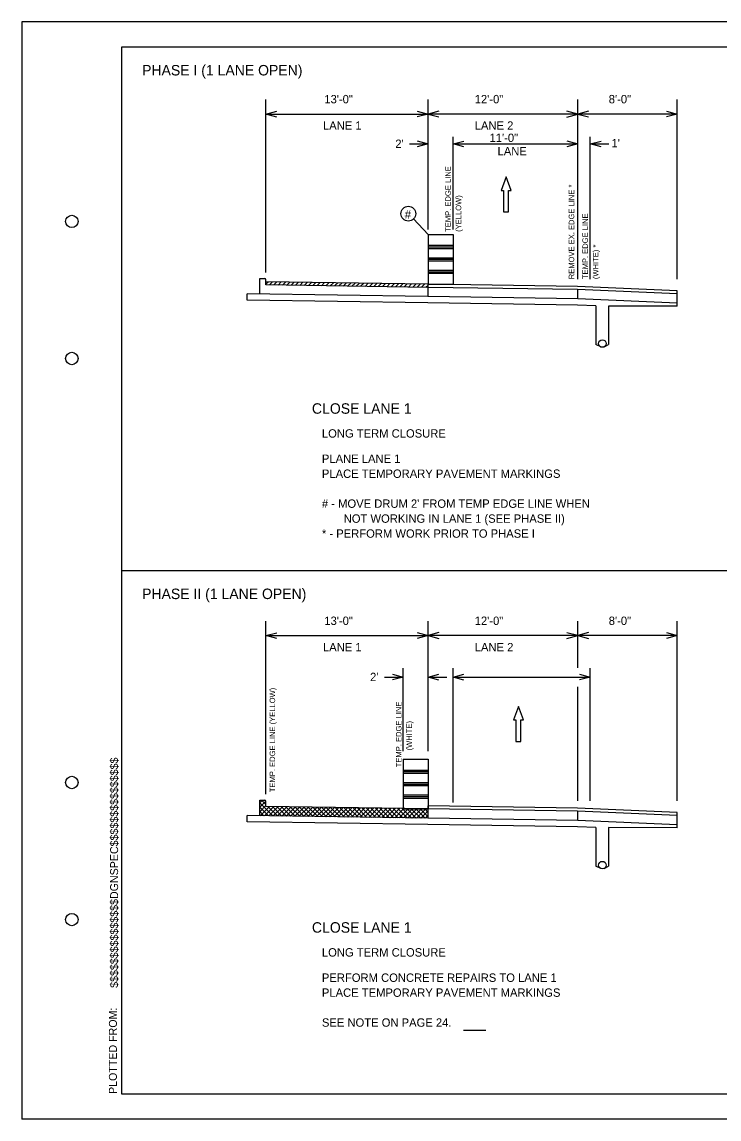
# Model space of a CAD drawing. Extents: x -161 to 291, y -369 to 173.
# Drawn here: x -160.7 to -104.8, y -273.4 to -185.4 of the extents above; entities that cross this region are included whole.
import ezdxf

# ---------------------------------------------------------------- set-up
doc = ezdxf.new("R2010")
doc.units = 0
for name, color, linetype in [('Level 1', 7, 'Continuous'), ('Level 11', 7, 'Continuous'), ('Level 21', 7, 'Continuous'), ('Level 25', 7, 'Continuous'), ('Level 26', 7, 'Continuous'), ('Level 6', 7, 'Continuous'), ('Level 7', 7, 'Continuous')]:
    doc.layers.add(name, color=color, linetype=linetype)

msp = doc.modelspace()

# ---------------------------------------------------------------- linework, layer by layer
at = {"layer": 'Level 1'}
for p, q in [((-160.725, -185.431), (-160.725, -273.422)), ((-24.739, -185.431), (-160.725, -185.431)), ((-152.726, -271.422), (-152.726, -187.43)), ((-152.726, -187.43), (-26.739, -187.43)), ((-152.726, -229.426), (-30.738, -229.426)), ((-26.739, -271.422), (-152.726, -271.422)), ((-24.739, -273.422), (-160.725, -273.422))]:
    msp.add_line(p, q, dxfattribs=at)
for centre in [(-156.725, -201.429), (-156.725, -212.428), (-156.725, -246.424), (-156.725, -257.423)]:
    msp.add_circle(centre, 0.5, dxfattribs=at)
at = {"layer": 'Level 11'}
for p, q in [((-141.66, -207.256), (-141.66, -206.015)), ((-141.66, -206.015), (-141.243, -206.015)), ((-141.16, -206.515), (-141.16, -206.098)), ((-128.16, -206.466), (-141.16, -206.265)), ((-141.16, -206.448), (-140.981, -206.268)), ((-128.16, -206.716), (-141.16, -206.515)), ((-140.879, -206.52), (-140.633, -206.274)), ((-140.531, -206.525), (-140.284, -206.279)), ((-140.182, -206.531), (-139.936, -206.284)), ((-139.834, -206.536), (-139.588, -206.29)), ((-139.486, -206.541), (-139.24, -206.295)), ((-139.138, -206.547), (-138.892, -206.301)), ((-138.79, -206.552), (-138.543, -206.306)), ((-138.442, -206.557), (-138.195, -206.311)), ((-138.093, -206.563), (-137.847, -206.317)), ((-137.745, -206.568), (-137.499, -206.322)), ((-137.397, -206.574), (-137.151, -206.327)), ((-137.049, -206.579), (-136.803, -206.333)), ((-136.701, -206.584), (-136.454, -206.338)), ((-136.352, -206.59), (-136.106, -206.344)), ((-136.004, -206.595), (-135.758, -206.349)), ((-135.656, -206.6), (-135.41, -206.354)), ((-135.308, -206.606), (-135.062, -206.36)), ((-134.96, -206.611), (-134.714, -206.365)), ((-134.612, -206.617), (-134.365, -206.37)), ((-134.263, -206.622), (-134.017, -206.376)), ((-133.915, -206.627), (-133.669, -206.381)), ((-133.567, -206.633), (-133.321, -206.387)), ((-133.219, -206.638), (-132.973, -206.392)), ((-132.871, -206.644), (-132.625, -206.397)), ((-132.523, -206.649), (-132.276, -206.403)), ((-132.174, -206.654), (-131.928, -206.408)), ((-131.826, -206.66), (-131.58, -206.413)), ((-131.478, -206.665), (-131.232, -206.419)), ((-131.13, -206.67), (-130.884, -206.424)), ((-130.782, -206.676), (-130.535, -206.43)), ((-130.434, -206.681), (-130.187, -206.435)), ((-130.085, -206.687), (-129.839, -206.44)), ((-129.737, -206.692), (-129.491, -206.446)), ((-129.389, -206.697), (-129.143, -206.451)), ((-129.041, -206.703), (-128.795, -206.456)), ((-128.693, -206.708), (-128.446, -206.462)), ((-128.344, -206.713), (-128.16, -206.529)), ((-128.16, -206.716), (-128.16, -206.466)), ((-116.184, -206.901), (-128.16, -206.716)), ((-128.16, -207.464), (-128.16, -206.716)), ((-116.187, -206.651), (-128.156, -206.466)), ((-108.187, -206.986), (-116.187, -206.651)), ((-128.176, -207.464), (-142.661, -207.24)), ((-142.66, -207.74), (-142.66, -207.24)), ((-116.167, -207.649), (-128.16, -207.464)), ((-108.187, -207.236), (-116.184, -206.901)), ((-108.19, -207.984), (-116.167, -207.649)), ((-116.16, -207.65), (-116.16, -206.902)), ((-108.187, -208.234), (-108.187, -206.986)), ((-128.176, -207.964), (-142.661, -207.74)), ((-116.185, -208.149), (-128.174, -207.964)), ((-114.713, -208.211), (-116.185, -208.149)), ((-114.709, -208.211), (-114.709, -211.302)), ((-113.709, -208.214), (-113.709, -211.292)), ((-108.187, -208.234), (-113.709, -208.214)), ((-114.322, -211.494), (-114.709, -211.302)), ((-114.032, -211.483), (-113.709, -211.291)), ((-141.66, -249.092), (-141.66, -247.851)), ((-141.66, -247.851), (-141.243, -247.851)), ((-141.16, -248.351), (-141.16, -247.934)), ((-128.16, -248.552), (-141.16, -248.351)), ((-128.16, -248.552), (-128.16, -248.302)), ((-116.184, -248.737), (-128.16, -248.552)), ((-128.16, -249.3), (-128.16, -248.552)), ((-116.187, -248.487), (-128.156, -248.302)), ((-108.187, -248.822), (-116.187, -248.487)), ((-108.187, -249.072), (-116.184, -248.737)), ((-116.16, -249.486), (-116.16, -248.738)), ((-108.187, -250.07), (-108.187, -248.822)), ((-128.176, -249.3), (-142.661, -249.076)), ((-128.176, -249.8), (-142.661, -249.576)), ((-142.66, -249.576), (-142.66, -249.076)), ((-116.185, -249.985), (-128.174, -249.8)), ((-116.167, -249.485), (-128.16, -249.3)), ((-108.19, -249.82), (-116.167, -249.485)), ((-114.713, -250.047), (-116.185, -249.985)), ((-114.709, -250.047), (-114.709, -253.138)), ((-113.709, -250.05), (-113.709, -253.128)), ((-108.187, -250.07), (-113.709, -250.05)), ((-114.322, -253.33), (-114.709, -253.138)), ((-114.032, -253.319), (-113.709, -253.127))]:
    msp.add_line(p, q, dxfattribs=at)
for centre in [(-114.187, -211.222), (-114.187, -253.058)]:
    msp.add_circle(centre, 0.304, dxfattribs=at)
for centre in [(-141.243, -206.098), (-141.243, -247.934)]:
    msp.add_arc(centre, 0.083, 0, 90, dxfattribs=at)
at = {"layer": 'Level 21'}
for p, q in [((-141.66, -248.066), (-141.445, -247.851)), ((-141.66, -248.42), (-141.161, -247.921)), ((-141.66, -248.05), (-140.602, -249.108)), ((-141.505, -247.851), (-141.16, -248.197)), ((-141.66, -248.774), (-141.16, -248.274)), ((-141.66, -248.404), (-140.962, -249.102)), ((-141.66, -248.757), (-141.321, -249.097)), ((-141.625, -249.092), (-140.888, -248.356)), ((-141.277, -249.098), (-140.54, -248.361)), ((-141.003, -248.354), (-140.243, -249.114)), ((-140.929, -249.103), (-140.192, -248.366)), ((-140.644, -248.359), (-139.884, -249.119)), ((-140.581, -249.108), (-139.844, -248.372)), ((-140.285, -248.365), (-139.525, -249.125)), ((-140.232, -249.114), (-139.496, -248.377)), ((-139.926, -248.37), (-139.166, -249.13)), ((-139.884, -249.119), (-139.148, -248.382)), ((-139.567, -248.376), (-138.807, -249.136)), ((-139.536, -249.124), (-138.799, -248.388)), ((-139.208, -248.382), (-138.448, -249.141)), ((-139.188, -249.13), (-138.451, -248.393)), ((-138.848, -248.387), (-138.089, -249.147)), ((-138.84, -249.135), (-138.103, -248.399)), ((-138.491, -249.141), (-137.755, -248.404)), ((-138.489, -248.393), (-137.73, -249.152)), ((-138.143, -249.146), (-137.407, -248.409)), ((-138.13, -248.398), (-137.371, -249.158)), ((-137.795, -249.151), (-137.059, -248.415)), ((-137.771, -248.404), (-137.011, -249.163)), ((-137.447, -249.157), (-136.71, -248.42)), ((-137.412, -248.409), (-136.652, -249.169)), ((-137.099, -249.162), (-136.362, -248.425)), ((-137.053, -248.415), (-136.293, -249.175)), ((-136.751, -249.167), (-136.014, -248.431)), ((-136.694, -248.42), (-135.934, -249.18)), ((-136.402, -249.173), (-135.666, -248.436)), ((-136.335, -248.426), (-135.575, -249.186)), ((-136.054, -249.178), (-135.318, -248.442)), ((-135.976, -248.431), (-135.216, -249.191)), ((-135.706, -249.184), (-134.97, -248.447)), ((-135.617, -248.437), (-134.857, -249.197)), ((-135.358, -249.189), (-134.621, -248.452)), ((-135.257, -248.443), (-134.498, -249.202)), ((-135.01, -249.194), (-134.273, -248.458)), ((-134.898, -248.448), (-134.139, -249.208)), ((-134.662, -249.2), (-133.925, -248.463)), ((-134.539, -248.454), (-133.78, -249.213)), ((-134.313, -249.205), (-133.577, -248.469)), ((-134.18, -248.459), (-133.42, -249.219)), ((-133.965, -249.21), (-133.229, -248.474)), ((-133.821, -248.465), (-133.061, -249.224)), ((-133.617, -249.216), (-132.88, -248.479)), ((-133.462, -248.47), (-132.702, -249.23)), ((-133.269, -249.221), (-132.532, -248.485)), ((-133.103, -248.476), (-132.343, -249.236)), ((-132.921, -249.227), (-132.184, -248.49)), ((-132.744, -248.481), (-131.984, -249.241)), ((-132.573, -249.232), (-131.836, -248.495)), ((-132.385, -248.487), (-131.625, -249.247)), ((-132.224, -249.237), (-131.488, -248.501)), ((-132.025, -248.492), (-131.266, -249.252)), ((-131.876, -249.243), (-131.14, -248.506)), ((-131.666, -248.498), (-130.907, -249.258)), ((-131.528, -249.248), (-130.791, -248.512)), ((-131.307, -248.504), (-130.548, -249.263)), ((-131.18, -249.253), (-130.443, -248.517)), ((-130.948, -248.509), (-130.189, -249.269)), ((-130.832, -249.259), (-130.095, -248.522)), ((-130.589, -248.515), (-129.829, -249.274)), ((-130.483, -249.264), (-129.747, -248.528)), ((-130.23, -248.52), (-129.47, -249.28)), ((-130.135, -249.27), (-129.399, -248.533)), ((-129.871, -248.526), (-129.111, -249.285)), ((-129.787, -249.275), (-129.051, -248.538)), ((-129.512, -248.531), (-128.752, -249.291)), ((-129.439, -249.28), (-128.702, -248.544)), ((-129.153, -248.537), (-128.393, -249.297)), ((-129.091, -249.286), (-128.354, -248.549)), ((-128.794, -248.542), (-128.16, -249.176)), ((-128.743, -249.291), (-128.16, -248.709)), ((-128.434, -248.548), (-128.16, -248.822)), ((-128.394, -249.297), (-128.16, -249.062))]:
    msp.add_line(p, q, dxfattribs=at)
at = {"layer": 'Level 25'}
for p, q in [((-128.156, -202.466), (-128.156, -206.466)), ((-128.156, -202.466), (-126.156, -202.466)), ((-126.156, -202.466), (-126.156, -206.466)), ((-128.156, -203.341), (-126.156, -203.341)), ((-128.156, -203.466), (-126.156, -203.466)), ((-128.156, -203.591), (-126.156, -203.591)), ((-128.156, -204.341), (-126.156, -204.341)), ((-128.156, -204.466), (-126.156, -204.466)), ((-128.156, -204.591), (-126.156, -204.591)), ((-128.156, -205.341), (-126.156, -205.341)), ((-128.156, -205.466), (-126.156, -205.466)), ((-128.156, -205.591), (-126.156, -205.591)), ((-128.156, -206.466), (-126.156, -206.466)), ((-130.16, -244.552), (-130.16, -248.552)), ((-130.16, -244.552), (-128.16, -244.552)), ((-128.16, -244.552), (-128.16, -248.552)), ((-130.16, -245.427), (-128.16, -245.427)), ((-130.16, -245.552), (-128.16, -245.552)), ((-130.16, -245.677), (-128.16, -245.677)), ((-130.16, -246.427), (-128.16, -246.427)), ((-130.16, -246.552), (-128.16, -246.552)), ((-130.16, -246.677), (-128.16, -246.677)), ((-130.16, -247.427), (-128.16, -247.427)), ((-130.16, -247.552), (-128.16, -247.552)), ((-130.16, -247.677), (-128.16, -247.677)), ((-130.16, -248.552), (-128.16, -248.552))]:
    msp.add_line(p, q, dxfattribs=at)
at = {"layer": 'Level 26'}
for p, q in [((-141.16, -205.539), (-141.16, -191.656)), ((-128.16, -202.078), (-128.16, -191.656)), ((-116.16, -206.069), (-116.16, -191.656)), ((-108.187, -206.068), (-108.187, -191.656)), ((-141.16, -192.816), (-128.16, -192.816)), ((-116.16, -192.816), (-128.16, -192.816)), ((-108.187, -192.816), (-116.16, -192.816)), ((-129.66, -195.211), (-128.16, -195.211)), ((-126.16, -202.078), (-126.16, -194.636)), ((-126.16, -195.211), (-116.16, -195.211)), ((-115.16, -206.069), (-115.16, -194.636)), ((-115.16, -195.211), (-113.66, -195.211)), ((-128.156, -202.466), (-129.325, -201.232)), ((-141.16, -247.374), (-141.16, -233.492)), ((-128.16, -243.914), (-128.16, -233.492)), ((-116.16, -237.228), (-116.16, -233.492)), ((-108.187, -247.904), (-108.187, -233.492)), ((-141.16, -234.652), (-128.16, -234.652)), ((-116.16, -234.652), (-128.16, -234.652)), ((-108.187, -234.652), (-116.16, -234.652)), ((-130.16, -243.914), (-130.16, -237.261)), ((-126.16, -248.035), (-126.16, -237.261)), ((-115.16, -247.905), (-115.16, -237.261)), ((-131.66, -237.972), (-130.16, -237.972)), ((-128.16, -237.972), (-126.66, -237.972)), ((-126.16, -237.972), (-115.16, -237.972)), ((-116.16, -247.905), (-116.16, -238.748))]:
    msp.add_line(p, q, dxfattribs=at)
for points in [[(-140.294, -193.055), (-141.16, -192.816), (-140.294, -192.585)], [(-129.026, -192.576), (-128.16, -192.816), (-129.026, -193.047)], [(-127.294, -192.576), (-128.16, -192.816), (-127.294, -193.047)], [(-117.029, -193.056), (-116.16, -192.816), (-117.029, -192.584)], [(-115.294, -192.576), (-116.16, -192.816), (-115.294, -193.047)], [(-109.055, -192.576), (-108.187, -192.816), (-109.055, -193.047)], [(-129.026, -194.972), (-128.16, -195.211), (-129.026, -195.442)], [(-125.294, -195.45), (-126.16, -195.211), (-125.294, -194.98)], [(-117.026, -194.972), (-116.16, -195.211), (-117.026, -195.442)], [(-114.294, -195.45), (-115.16, -195.211), (-114.294, -194.98)], [(-140.294, -234.891), (-141.16, -234.652), (-140.294, -234.421)], [(-129.026, -234.412), (-128.16, -234.652), (-129.026, -234.883)], [(-127.294, -234.412), (-128.16, -234.652), (-127.294, -234.883)], [(-117.029, -234.891), (-116.16, -234.652), (-117.029, -234.42)], [(-115.294, -234.412), (-116.16, -234.652), (-115.294, -234.883)], [(-109.055, -234.412), (-108.187, -234.652), (-109.055, -234.883)], [(-131.026, -237.733), (-130.16, -237.972), (-131.026, -238.203)], [(-127.294, -238.211), (-128.16, -237.972), (-127.294, -237.741)], [(-125.294, -238.211), (-126.16, -237.972), (-125.294, -237.741)], [(-116.026, -237.733), (-115.16, -237.972), (-116.026, -238.203)]]:
    msp.add_lwpolyline(points, dxfattribs=at)
msp.add_circle((-129.747, -200.809), 0.597, dxfattribs=at)
at = {"layer": 'Level 6'}
msp.add_line((-125.334, -266.28), (-123.527, -266.28), dxfattribs=at)
at = {"layer": 'Level 7'}
for p, q in [((-121.914, -197.866), (-122.311, -198.937)), ((-121.511, -198.937), (-121.914, -197.866)), ((-122.311, -198.937), (-122.106, -198.937)), ((-122.106, -198.937), (-122.106, -200.664)), ((-121.716, -200.664), (-121.716, -198.937)), ((-121.716, -198.937), (-121.511, -198.937)), ((-122.106, -200.664), (-121.716, -200.664)), ((-120.923, -240.33), (-121.32, -241.4)), ((-120.52, -241.4), (-120.923, -240.33)), ((-121.32, -241.4), (-121.115, -241.4)), ((-121.115, -241.4), (-121.115, -243.128)), ((-120.725, -243.128), (-120.725, -241.4)), ((-120.725, -241.4), (-120.52, -241.4)), ((-121.115, -243.128), (-120.725, -243.128))]:
    msp.add_line(p, q, dxfattribs=at)

# ---------------------------------------------------------------- texts
at = {"layer": 'Level 1'}
for s, p in [('$$$$$$$$$$$$$$$DGNSPEC$$$$$$$$$$$$$$$', (-153.016, -262.898)), ('PLOTTED FROM:', (-153.112, -271.408))]:
    msp.add_text(s, height=0.63859, rotation=90, dxfattribs=at).set_placement(p)
at = {"layer": 'Level 26'}
for s, p in [('13\'-0"', (-136.479, -191.958)), ('12\'-0"', (-124.422, -191.958)), ('8\'-0"', (-113.677, -191.958)), ('LANE 1', (-136.59, -194.075)), ('LANE 2', (-124.422, -194.075)), ('11\'-0"', (-123.236, -195.061)), ("2'", (-130.789, -195.538)), ("1'", (-113.458, -195.488)), ('LANE', (-122.59, -196.133)), ('#', (-130.03, -201.212)), ('13\'-0"', (-136.479, -233.794)), ('12\'-0"', (-124.422, -233.794)), ('8\'-0"', (-113.677, -233.794)), ('LANE 1', (-136.59, -235.911)), ('LANE 2', (-124.422, -235.911)), ("2'", (-132.815, -238.299))]:
    msp.add_text(s, height=0.672, dxfattribs=at).set_placement(p)
for s, p in [('TEMP. EDGE LINE', (-126.345, -202.266)), ('REMOVE EX. EDGE LINE *', (-116.443, -206.069)), ('(YELLOW) ', (-125.505, -202.266)), ('TEMP. EDGE LINE', (-115.346, -206.055)), ('(WHITE) *', (-114.506, -206.055)), ('TEMP. EDGE LINE (YELLOW) ', (-140.425, -247.204)), ('TEMP. EDGE LINE', (-130.296, -245.207)), ('        (WHITE) ', (-129.456, -245.207))]:
    msp.add_text(s, height=0.44, rotation=90, dxfattribs=at).set_placement(p)
at = {"layer": 'Level 6'}
for s, height, p in [('PHASE I (1 LANE OPEN)', 0.84, (-151.092, -189.722)), ('CLOSE LANE 1', 0.84, (-137.474, -216.854)), ('LONG TERM CLOSURE', 0.672, (-136.674, -218.77)), ('PLANE LANE 1 ', 0.672, (-136.674, -220.798)), ('PLACE TEMPORARY PAVEMENT MARKINGS', 0.672, (-136.674, -221.998)), ("# - MOVE DRUM 2' FROM TEMP EDGE LINE WHEN", 0.672, (-136.674, -224.398)), ('       NOT WORKING IN LANE 1 (SEE PHASE II)', 0.672, (-136.674, -225.598)), ('* - PERFORM WORK PRIOR TO PHASE I', 0.672, (-136.674, -226.798)), ('PHASE II (1 LANE OPEN)', 0.84, (-151.092, -231.718)), ('CLOSE LANE 1', 0.84, (-137.474, -258.474)), ('LONG TERM CLOSURE', 0.672, (-136.674, -260.39)), ('PERFORM CONCRETE REPAIRS TO LANE 1', 0.672, (-136.674, -262.418)), ('PLACE TEMPORARY PAVEMENT MARKINGS', 0.672, (-136.674, -263.617)), ('SEE NOTE ON PAGE 24.', 0.672, (-136.674, -266.017))]:
    msp.add_text(s, height=height, dxfattribs=at).set_placement(p)

doc.saveas('drawing.dxf')
